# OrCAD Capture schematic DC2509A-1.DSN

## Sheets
1 PAGE2: size Custom; title: MULTI-SOURCE EH DEMOBOARD WITH BATTERY CHARGERS; rev: 1; note: DEMO CIRCUIT 2509A
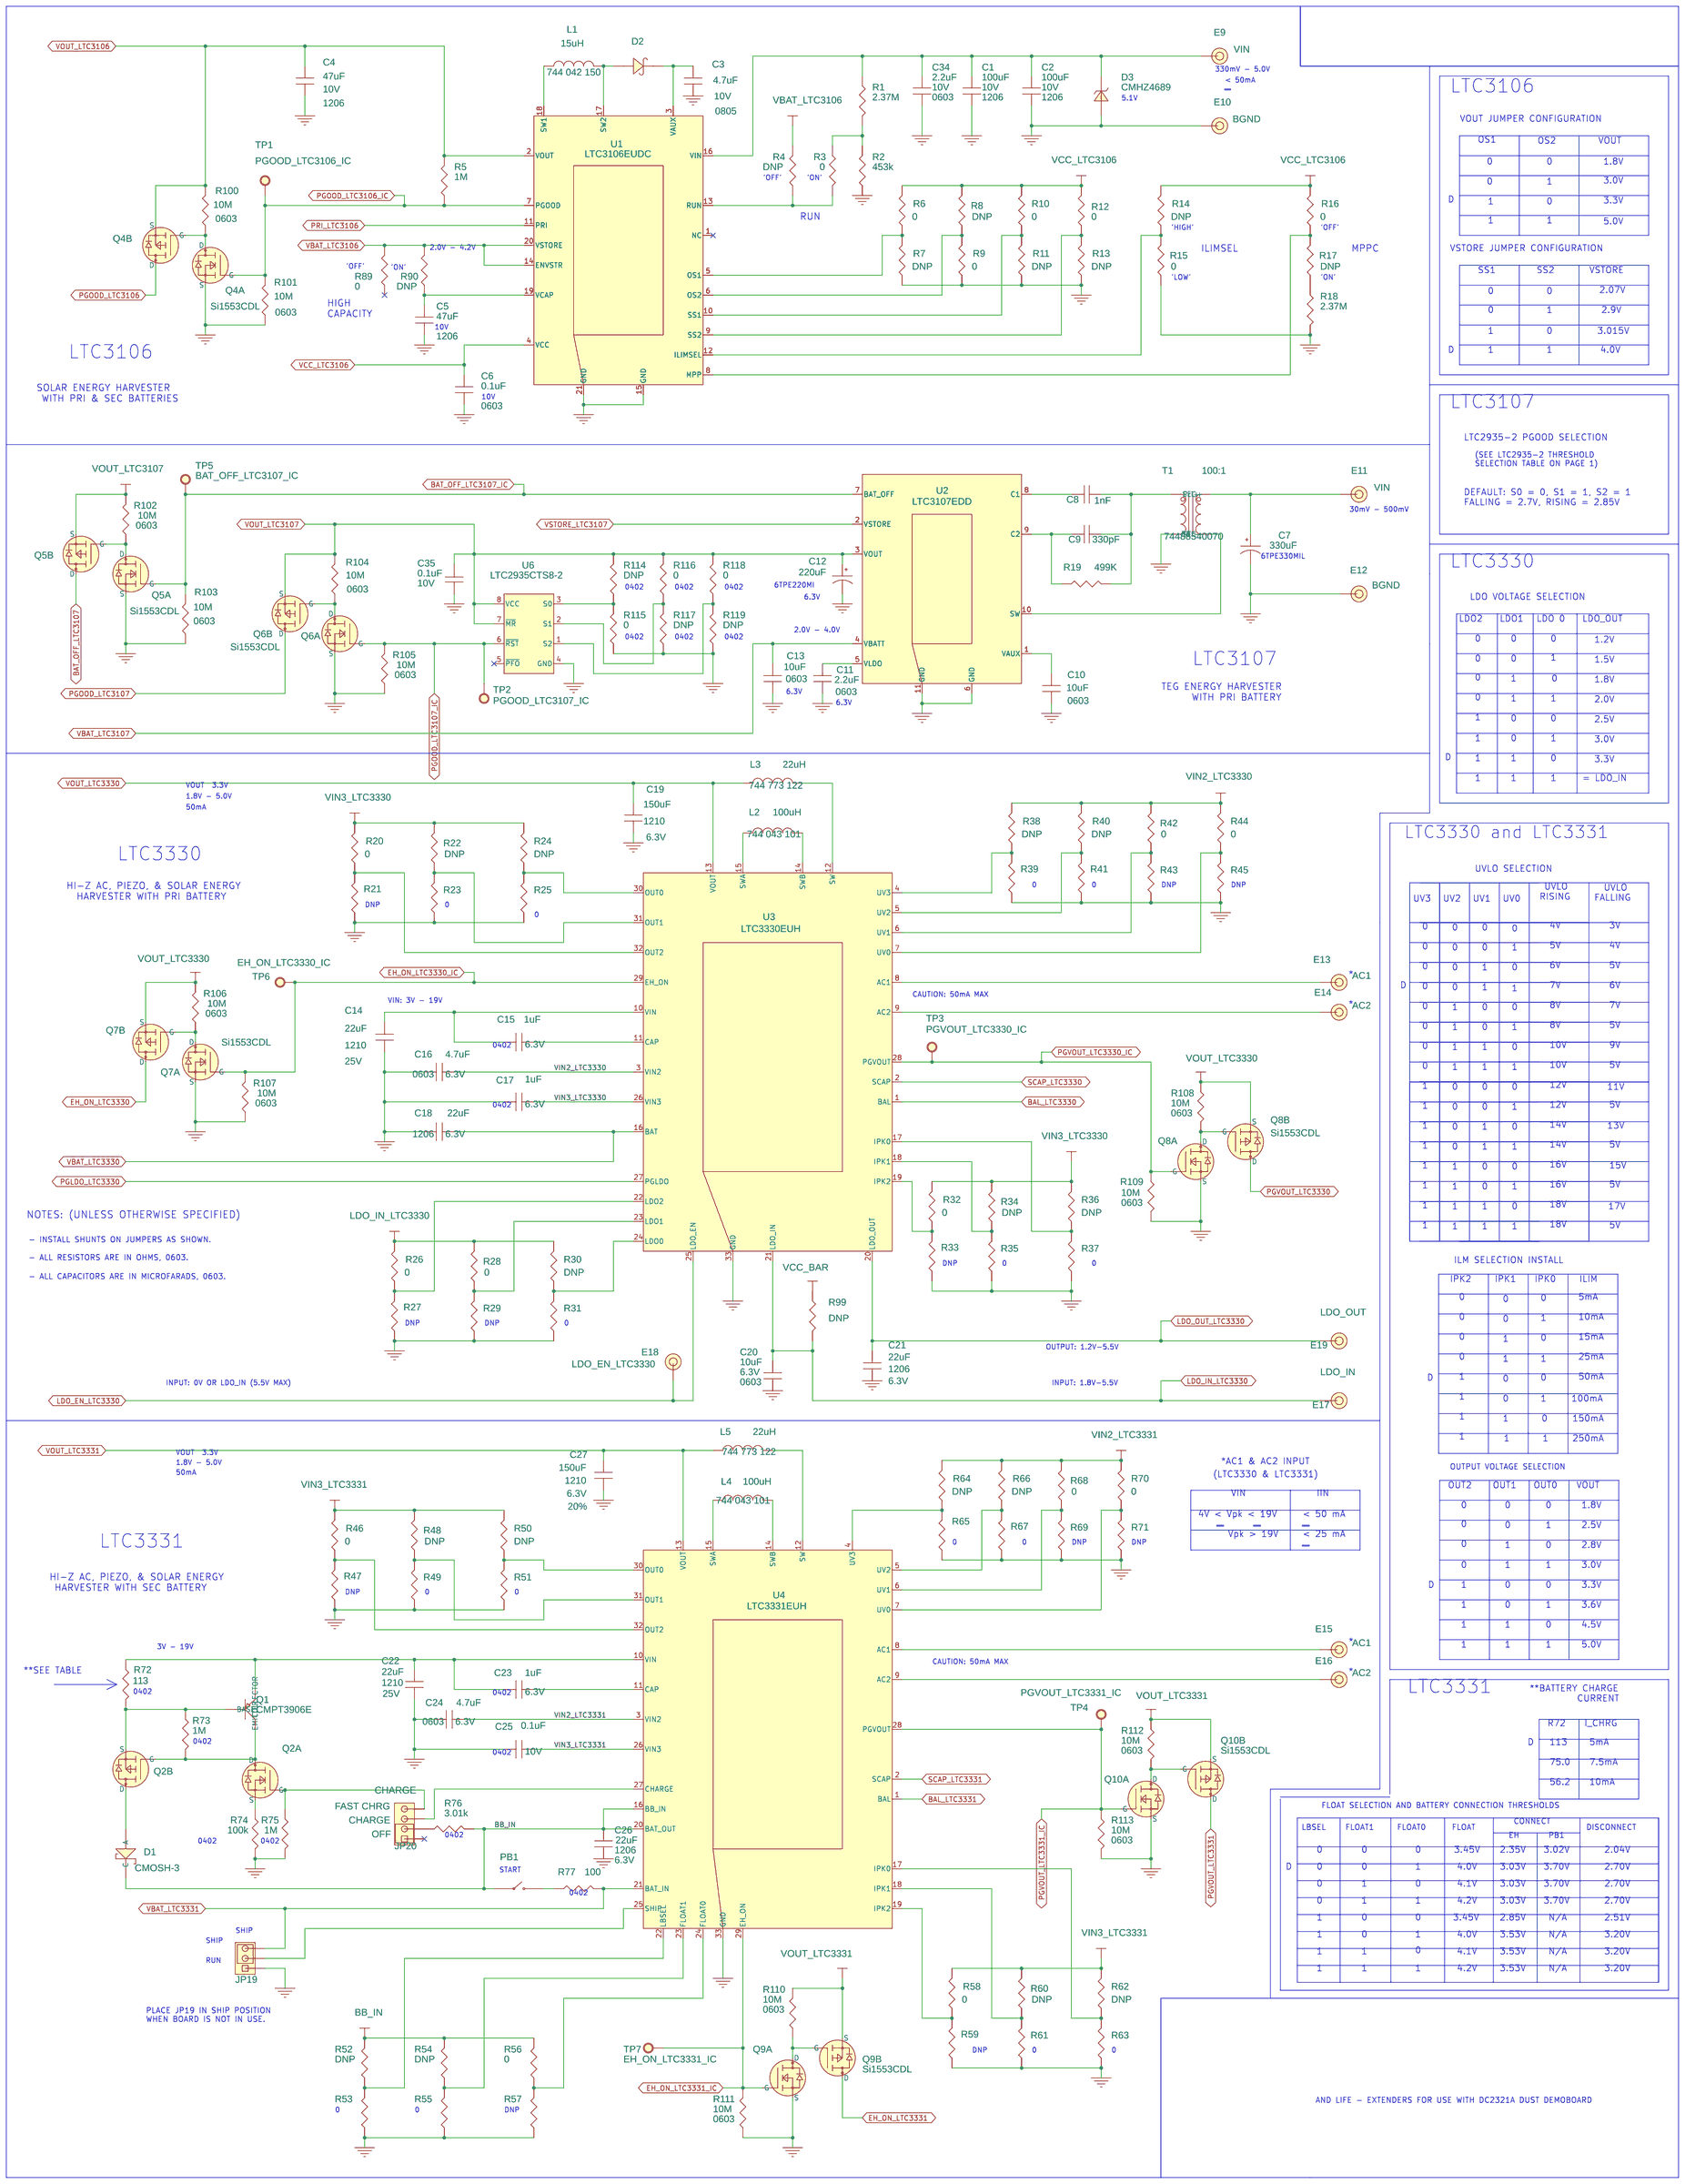
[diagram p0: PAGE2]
2 PAGE1: size Custom
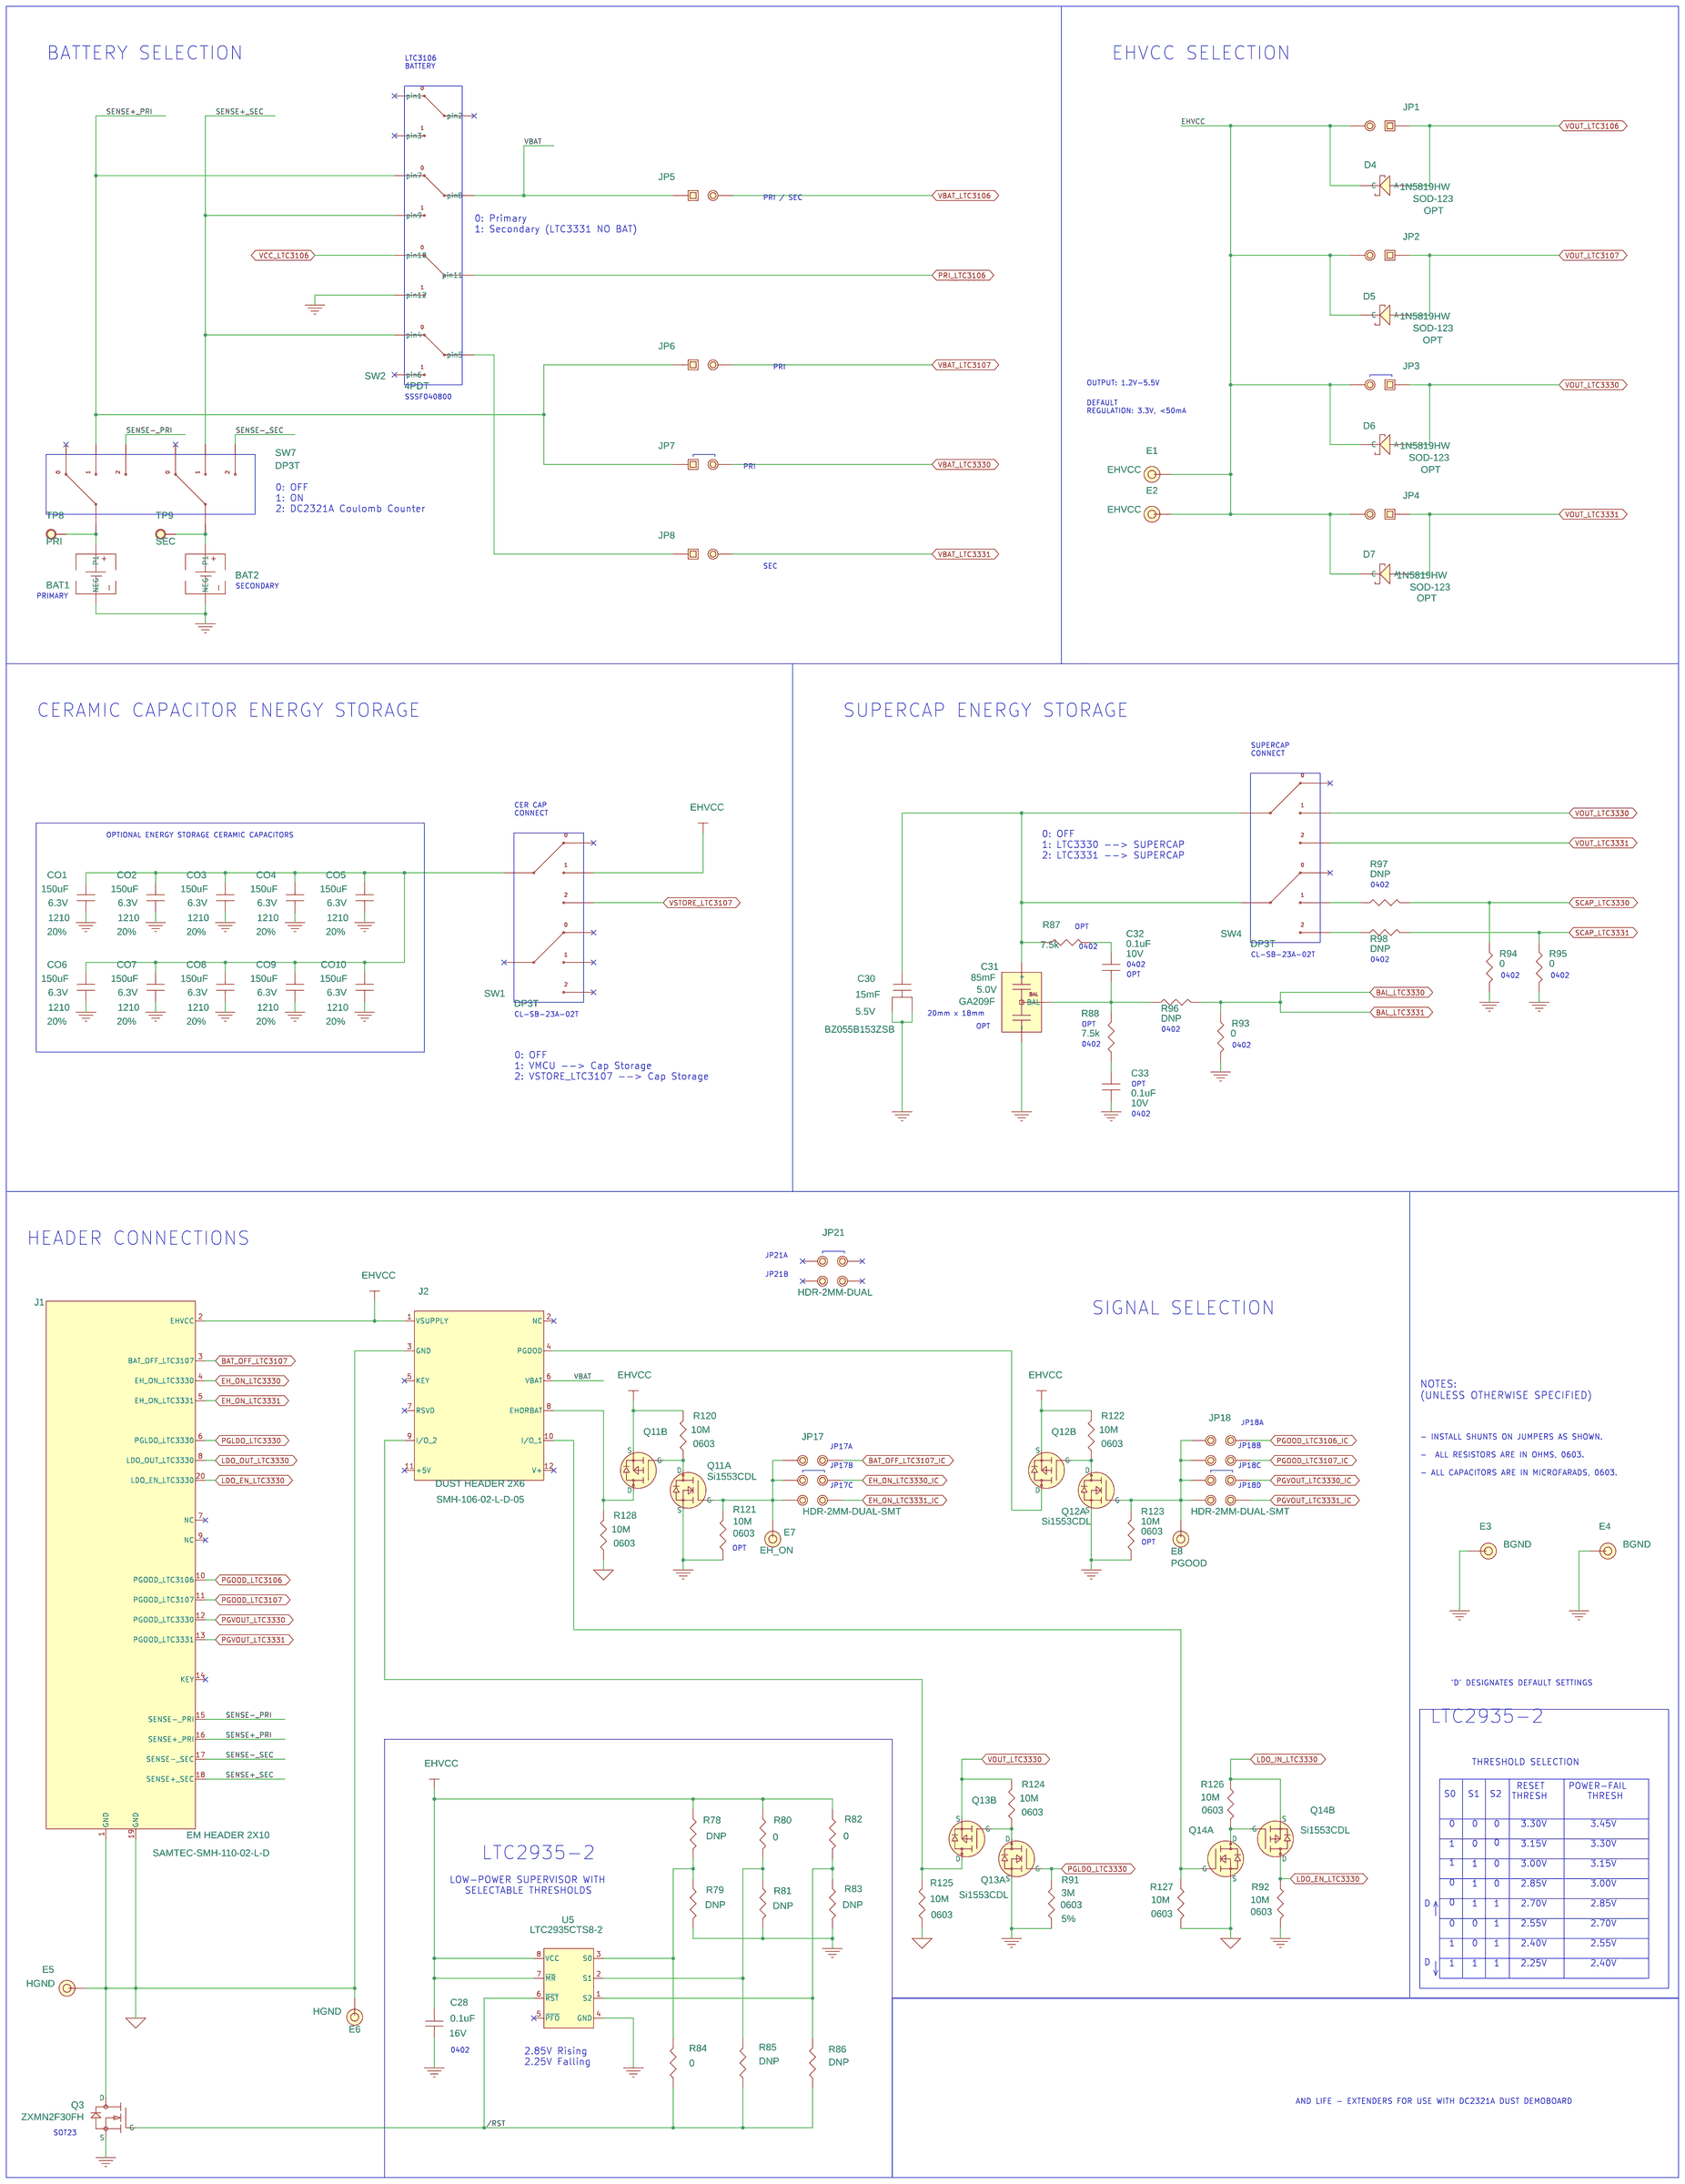
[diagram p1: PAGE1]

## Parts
sheet PAGE1
BAT1  CR2032  [BATTHOLD-WU-79527141]
BAT2  SMTU2032-LF  [BATTHOLD-WU-79527141]
C28  0.1uF  [0402-SMALL]
C30  15mF  [CAPAVX-BZ05]
C31  85mF  [CAP\CAP-XX\HA-202F]
C32  0.1uF  [0402]
C33  0.1uF  [0402]
CO1  150uF  [1210]
CO2  150uF  [1210]
CO3  150uF  [1210]
CO4  150uF  [1210]
CO5  150uF  [1210]
CO6  150uF  [1210]
CO7  150uF  [1210]
CO8  150uF  [1210]
CO9  150uF  [1210]
CO10  150uF  [1210]
D4  1N5819HW  [SOD-123]
D5  1N5819HW  [SOD-123]
D6  1N5819HW  [SOD-123]
D7  1N5819HW  [SOD-123]
E1  EHVCC  [MILL-MAX-2308]
E2  EHVCC  [MILL-MAX-2308]
E3  BGND  [MILL-MAX-2308]
E4  BGND  [MILL-MAX-2308]
E5  HGND  [MILL-MAX-2308]
E6  HGND  [MILL-MAX-2308]
E7  EH_ON  [MILL-MAX-2308]
E8  PGOOD  [MILL-MAX-2308]
J1  EM HEADER 2X10  [SAMTEC-SMH-110-02-L-D]
J2  DUST HEADER 2X6  [SMH-12PIN-100-DUST]
JP1  Sgl. Row 3 Pins 2mm Ctrs.  [TMM-102-01-T-S-SM]
JP2  Sgl. Row 3 Pins 2mm Ctrs.  [TMM-102-01-T-S-SM]
JP3  Sgl. Row 3 Pins 2mm Ctrs.  [TMM-102-01-T-S-SM]
JP4  Sgl. Row 3 Pins 2mm Ctrs.  [TMM-102-01-T-S-SM]
JP5  Sgl. Row 3 Pins 2mm Ctrs.  [TMM-102-01-T-S-SM]
JP6  Sgl. Row 3 Pins 2mm Ctrs.  [TMM-102-01-T-S-SM]
JP7  Sgl. Row 3 Pins 2mm Ctrs.  [TMM-102-01-T-S-SM]
JP8  Sgl. Row 3 Pins 2mm Ctrs.  [TMM-102-01-T-S-SM]
JP17  2pins 2mm Ctrs.  [HDR-WURTH-2MM-DUAL-SMT-62100621921]
JP18  2pins 2mm Ctrs.  [HDR-WURTH-2MM-DUAL-SMT-62100821921]
JP21  2pins 2mm Ctrs.  [WURTH_2MM_DUAL_PIN_HDR]
Q3  ZXMN2F30FH  [ZETEX-SOT23]
Q11  Si1553DL  [SC70-6]  (sections A,B)
Q12  Si1553DL  [SC70-6]  (sections A,B)
Q13  Si1553DL  [SC70-6]  (sections A,B)
Q14  Si1553DL  [SC70-6]  (sections A,B)
R78  DNP  [0402-SMALL]
R79  DNP  [0402-SMALL]
R80  0  [0402-SMALL]
R81  DNP  [0402-SMALL]
R82  0  [0402-SMALL]
R83  DNP  [0402-SMALL]
R84  0  [0402-SMALL]
R85  DNP  [0402-SMALL]
R86  DNP  [0402-SMALL]
R87  7.5k  [0402]
R88  7.5k  [0402]
R91  3M  [0603]
R92  10M  [0603]
R93  0  [0402-SMALL]
R94  0  [0402-SMALL]
R95  0  [0402-SMALL]
R96  DNP  [0402-SMALL]
R97  DNP  [0402-SMALL]
R98  DNP  [0402-SMALL]
R120  10M  [0603]
R121  10M  [0603]
R122  10M  [0603]
R123  10M  [0603]
R124  10M  [0603]
R125  10M  [0603]
R126  10M  [0603]
R127  10M  [0603]
R128  10M  [0603]
SW1  DP3T  [SLIDE_SW-DP3T-CL-SB-23A-02T]
SW2  4PDT  [SW-VERTICAL-4PDT-SSSF040800]
SW4  DP3T  [SLIDE_SW-DP3T-CL-SB-23A-02T]
SW7  DP3T  [SLIDE_SW-DP3T-CL-SB-23A-02T]
TP8  PRI  [TP]
TP9  SEC  [TP]
U5  LTC2935CTS8-2  [SOT23-8L]
sheet PAGE2
C1  100uF  [1206]
C2  100uF  [1206]
C3  4.7uF  [0805]
C4  47uF  [1206]
C5  47uF  [1206]
C6  0.1uF  [0603]
C7  330uF  [POSCAP-SANYO-TPC-D2]
C8  1nF  [0603]
C9  330pF  [0603]
C10  10uF  [0603]
C11  2.2uF  [0603]
C12  220uF  [POSCAP-SANYO-TPC-D2]
C13  10uF  [0603]
C14  22uF  [1210]
C15  1uF  [0402]
C16  4.7uF  [0603]
C17  1uF  [0402]
C18  22uF  [1206]
C19  150uF  [1210]
C20  10uF  [0603]
C21  22uF  [1206]
C22  22uF  [1210]
C23  1uF  [0402-SMALL]
C24  4.7uF  [0603]
C25  0.1uF  [0402-SMALL]
C26  22uF  [1206]
C27  150uF  [1210]
C34  2.2uF  [0603]
C35  0.1uF  [0402-SMALL]
D1  CMOSH-3  [DIODE-SHOTTKY-CMOSH-3]
D2  1A/20V  [SOD323-NXP]
D3  CMHZ4689  [SOD-123]
E9  VIN  [MILL-MAX-2308]
E10  BGND  [MILL-MAX-2308]
E11  VIN  [MILL-MAX-2308]
E12  BGND  [MILL-MAX-2308]
E13  AC1  [MILL-MAX-2308]
E14  AC2  [MILL-MAX-2308]
E15  AC1  [MILL-MAX-2308]
E16  AC2  [MILL-MAX-2308]
E17  LDO_IN  [MILL-MAX-2308]
E18  LDO_EN_LTC3330  [MILL-MAX-2308]
E19  LDO_OUT  [MILL-MAX-2308]
JP19  HD1X3-079  [HD1X3-079]
JP20  HD1X4-079  [HD1X4-079]
L1  15uH  [IND-WE-744042150]
L2  100uH  [IND-WE-744043101]
L3  22uH  [IND-WE732773220]
L4  100uH  [IND-WE-744043101]
L5  22uH  [IND-WE732773220]
PB1  WURTH- 434 111 025 826  [SW-WURTH-434-111-025-826]
Q1  CMPT3906E  [SOT-23]
Q2  NDS9952A  [SUPERSOT-6]  (sections A,B)
Q4  Si1553DL  [SC70-6]  (sections A,B)
Q5  Si1553DL  [SC70-6]  (sections A,B)
Q6  Si1553DL  [SC70-6]  (sections A,B)
Q7  Si1553DL  [SC70-6]  (sections A,B)
Q8  Si1553DL  [SC70-6]  (sections A,B)
Q9  Si1553DL  [SC70-6]  (sections A,B)
Q10  Si1553DL  [SC70-6]  (sections A,B)
R1  2.37M  [0603]
R2  453k  [0603]
R3  0  [0603]
R4  DNP  [0603]
R5  1M  [0603]
R6  0  [0603]
R7  DNP  [0603]
R8  DNP  [0603]
R9  0  [0603]
R10  0  [0603]
R11  DNP  [0603]
R12  0  [0603]
R13  DNP  [0603]
R14  DNP  [0603]
R15  0  [0603]
R16  0  [0603]
R17  DNP  [0603]
R18  2.37M  [0603]
R19  499K  [0603]
R20  0  [0603]
R21  0  [0603]
R22  DNP  [0603]
R23  0  [0603]
R24  DNP  [0603]
R25  0  [0603]
R26  0  [0603]
R27  0  [0603]
R28  0  [0603]
R29  0  [0603]
R30  DNP  [0603]
R31  0  [0603]
R32  0  [0603]
R33  0  [0603]
R34  DNP  [0603]
R35  0  [0603]
R36  DNP  [0603]
R37  0  [0603]
R38  DNP  [0603]
R39  0  [0603]
R40  DNP  [0603]
R41  0  [0603]
R42  0  [0603]
R43  0  [0603]
R44  0  [0603]
R45  0  [0603]
R46  0  [0603]
R47  0  [0603]
R48  DNP  [0603]
R49  0  [0603]
R50  DNP  [0603]
R51  0  [0603]
R52  DNP  [0603]
R53  0  [0603]
R54  DNP  [0603]
R55  0  [0603]
R56  0  [0603]
R57  0  [0603]
R58  0  [0603]
R59  0  [0603]
R60  DNP  [0603]
R61  0  [0603]
R62  DNP  [0603]
R63  0  [0603]
R64  DNP  [0603]
R65  0  [0603]
R66  DNP  [0603]
R67  0  [0603]
R68  0  [0603]
R69  0  [0603]
R70  0  [0603]
R71  0  [0603]
R72  113  [0402-SMALL]
R73  1M  [0402-SMALL]
R74  100k  [0402-SMALL]
R75  1M  [0402-SMALL]
R76  3.01k  [0402-SMALL]
R77  100  [0402-SMALL]
R89  0  [0603]
R90  DNP  [0603]
R99  DNP  [0603]
R100  10M  [0603]
R101  10M  [0603]
R102  10M  [0603]
R103  10M  [0603]
R104  10M  [0603]
R105  10M  [0603]
R106  10M  [0603]
R107  10M  [0603]
R108  10M  [0603]
R109  10M  [0603]
R110  10M  [0603]
R111  10M  [0603]
R112  10M  [0603]
R113  10M  [0603]
R114  DNP  [0402-SMALL]
R115  0  [0402-SMALL]
R116  0  [0402-SMALL]
R117  DNP  [0402-SMALL]
R118  0  [0402-SMALL]
R119  DNP  [0402-SMALL]
T1  74488540070  [TRANS-WE-74488540070]
TP1  PGOOD_LTC3106_IC  [TP]
TP2  PGOOD_LTC3107_IC  [TP]
TP3  PGVOUT_LTC3330_IC  [TP]
TP4  PGVOUT_LTC3331_IC  [TP]
TP5  BAT_OFF_LTC3107_IC  [TP]
TP6  EH_ON_LTC3330_IC  [TP]
TP7  EH_ON_LTC3331_IC  [TP]
U1  LTC3106EUDC  [QFN20EUDC-3X4]
U2  LTC3107EDD  [DFN(10)3MMX3MM]
U3  LTC3330EUH  [QFN(32)(UH)5MMX5MM]
U4  LTC3331EUH  [QFN(32)(UH)5MMX5MM]
U6  LTC2935CTS8-2  [SOT23-8L]

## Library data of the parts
BAT1 BAT2 = HU2032_2
C28 = C1608X5R0J475M: 1st Part Field: 16V; 2nd Part Field: 0402; 3rd Part Field: CHIP, X5R; 4th Part Field: MUR; 5th Part Field: GRM188R60J106ME47; 7th Part Field: CAP, X5R; Critical: T; Layer: T; MPN: GRM155R71C104KA88; Manufacturer: MUR; Populate: T; Size: 0402; Tempco: JIS-B; Tolerance: 10%; Voltage: 6.3Vmin
C30 = CAPACITOR_0: PART NUMBER: BZ055B153ZSB; Voltage: 5.5V
C31 = SUPERCAP_CAP-XX_HZ-SERIES_5: Part Number: GA209F; RATING: 5.0V; size: 20mm x 15mm
C25 C32 C33 = CAPACITOR: Voltage: 10V
C26 C27 CO1-CO10 = CAPACITOR: Tolerance: 20%; Voltage: 6.3V
D4-D7 = DIODE_SCHOTTKY: FIELD 99: OPT
E1-E19 = E_1: STATUS: 1.6V, 1.8V, 2.0V OR 2.5V @ 15A
J1 = HEADER2X7_9: OPN: SMH-110-02-L-D
J2 = HEADER2X7_0: OPN: SMH-106-02-L-D-05
JP1-JP8 = HD1X3_6: 10th Part Field: OFF; 12th Part Field: VSTORE; 9th Part Field: ON
JP17 = HDR-2MM-DUAL-SMT-62100821_0: 5th Part Field: 621 008 21; 9th Part Field: HDR-2MM-DUAL-SMT
JP18 = HDR-2MM-DUAL-SMT-62100821_2: 5th Part Field: 621 008 21; 9th Part Field: HDR-2MM-DUAL-SMT
JP21 = HDR-2MM-DUAL-SMT-62100821_3: 5th Part Field: 620 002 111 21; 9th Part Field: HDR-2MM-DUAL
Q3 = ZVN3306_0
Q4 Q5 Q8 Q9 Q11-Q14 = NDC7001C_5: COMPONENT: Si1553CDL
R3 R4 R6-R17 R20-R90 R92-R128 = RESISTOR
R91 = RESISTOR: TOLERANCE: 5%
SW1 SW4 = SW-DP3T_0
SW2 = SW-4PDT_3
SW7 = SW-DP3T_1
TP1-TP9 = Large_Turret_1
U5 U6 = MS8_5
C1 = Capacitor_1812_2: Voltage Rating: 10V
C2 = Capacitor_1812_1: Voltage Rating: 10V
C3 = Capacitor_0805: VOLTAGE RATING: 10V
C4 = Capacitor_1210_1: VOLTAGE RATING: 10V
C5 = Capacitor_1210
C6 = Capacitor_0805_1
C7 C12 = CAPACITOR_POL
C8 C9 = CAP_NP
C10 = Capacitor_0805_4
C11 = Capacitor_0805_2
C13 = Capacitor_0805_3
C14 C22 = CAPACITOR: Voltage: 25V
C15-C21 C23 C24 = CAPACITOR: Voltage: 6.3V
C34 = Capacitor_1812: Voltage Rating: 10V
C35 = C1608X5R0J475M: 1st Part Field: 10V; 2nd Part Field: 0402; 3rd Part Field: CHIP, X5R; 4th Part Field: MUR; 5th Part Field: GRM188R60J106ME47; 7th Part Field: CAP, X5R; Critical: T; Layer: T; MPN: GRM155R71C104KA88; Manufacturer: MUR; Populate: T; Size: 0402; Tempco: JIS-B; Tolerance: 10%; Voltage: 6.3Vmin
D1 = CMSH3-MA
D2 = PMEG2010EA_0: 6th Part Field: (OPT)
D3 = AD589_TO_1
JP19 = HD1X3_12
JP20 = HD1X4_2: TEXT: OFF; TEXT 4: CHARGE; TEXT2: CHARGE; TEXT3: FAST CHRG
L1 = INDUCTOR: PART NUMBER: 744 042 150
L2 L4 = INDUCTOR: PART NUMBER: 744 043 101
L3 L5 = INDUCTOR: PART NUMBER: 744 773 122
PB1 = SWITCH-TACT-SMD_0
Q1 = CMPT3906E
Q2 = NDC7001C_0
Q6 Q7 Q10 = NDC7001C_12: COMPONENT: Si1553CDL
R1 R2 R5 R18 R19 = R: V: 1%
T1 = LPR6235_0: TURNS RATIO: 100:1
U1 = LTC3106_21
U2 = LTC3107EDD_21
U3 = LTC3330EUH_48
U4 = LTC3330EUH_52

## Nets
GND: BAT1.2(NEG) BAT2.2(NEG) C1.2 C2.2 C3.2 C4.2 C5.2 C6.2 C7.2(-) C10.2 C11.2 C12.2(-) C13.2 C14.2 C16.1 C17.1 C18.1 C19.2 C20.2 C21.2 C22.2 C24.1 C25.1 C26.1 C27.2 C28.1 C30.2 C30.3 C31.1(-) C33.1 C34.2 C35.1 CO1.2 CO2.2 CO3.2 CO4.2 CO5.2 CO6.2 CO7.2 CO8.2 CO9.2 CO10.2 D3.2(A) E3.1(A) E4.1(A) E10.1(A) E12.1(A) JP19.1 Q3.2(S) Q4.1(S) Q5.1(S) Q6.1(S) Q7.1(S) Q8.1(S) Q9.1(S) Q10.1(S) Q11.1(S) Q12.1(S) Q13.1(S) R2.1 R7.1 R9.1 R11.1 R13.1 R15.1 R18.2 R21.1 R23.1 R25.1 R27.1 R29.1 R31.1 R33.1 R35.1 R37.1 R39.1 R41.1 R43.1 R45.1 R47.1 R49.1 R51.1 R53.1 R55.1 R57.1 R59.1 R61.1 R63.1 R65.1 R67.1 R69.1 R71.1 R74.2 R75.2 R79.2 R81.2 R83.2 R91.1 R92.2 R93.2 R94.2 R95.2 R101.2 R103.2 R105.2 R107.2 R109.2 R111.1 R113.2 R115.1 R117.1 R119.1 R121.2 R123.2 SW2.12(pin12) T1.3(SEC-) U1.15(GND) U1.21(GND) U2.6(GND) U2.11(GND) U3.33(GND) U4.33(GND) U5.4(GND) U6.4(GND)
GND_SIGNAL: E5.1(A) E6.1(A) J1.1(GND) J1.19(GND) J2.3(GND) Q3.3(D) Q14.1(S) R125.2 R127.2 R128.2
VBAT: J2.6(VBAT) JP5.1 SW2.8(pin8)
VBAT_LTC3106: JP5.2 R4.2 R89.2 R90.2 U1.14(ENVSTR) U1.20(VSTORE)
VBAT_LTC3107: C13.1 JP6.2 U2.4(VBATT)
VBAT_LTC3330: C18.2 JP7.2 U3.16(BAT)
VBAT_LTC3331: JP8.2 JP19.3 R77.2 U4.21(BAT_IN)
VCC_LTC3106: C6.1 R6.2 R8.2 R10.2 R12.2 R14.2 R16.2 SW2.10(pin10) U1.4(VCC)
VIN2_LTC3330: C16.2 R38.2 R40.2 R42.2 R44.2 U3.3(VIN2)
VIN2_LTC3331: C24.2 R64.2 R66.2 R68.2 R70.2 U4.3(VIN2)
VIN3_LTC3330: C17.2 R20.2 R22.2 R24.2 R32.2 R34.2 R36.2 U3.26(VIN3)
VIN3_LTC3331: C25.2 R46.2 R48.2 R50.2 R58.2 R60.2 R62.2 U4.26(VIN3)
/RST: Q3.1(G) R84.2 R85.2 R86.2 U5.6(~{RST})
BAL_LTC3330: R93.1 R96.2 U3.1(BAL) U4.1(BAL)
BAT_OFF_LTC3107: J1.3(BAT_OFF_LTC3107) Q5.3(D)
BAT_OFF_LTC3107_IC: JP17.1 Q5.2(G) R103.1 TP5.1 U2.7(BAT_OFF)
BB_IN: C26.2 D1.1(C) PB1.1(pin1) R52.2 R54.2 R56.2 R76.2 U4.16(BB_IN) U4.20(BAT_OUT)
EH_ON_LTC3330: J1.4(EH_ON_LTC3330) Q7.3(D)
EH_ON_LTC3330_IC: JP17.3 Q7.2(G) R107.1 TP6.1 U3.29(EH_ON)
EH_ON_LTC3331: J1.5(EH_ON_LTC3331) Q9.3(D)
EH_ON_LTC3331_IC: JP17.5 Q9.2(G) R111.2 TP7.1 U4.29(EH_ON)
EHVCC: C28.2 D4.1(C) D5.1(C) D6.1(C) D7.1(C) E1.1(A) E2.1(A) J1.2(EHVCC) J2.1(VSUPPLY) JP1.2 JP2.2 JP3.2 JP4.2 Q11.4(S) Q12.4(S) R78.1 R80.1 R82.1 R120.1 R122.1 SW1.2 U5.7(~{MR}) U5.8(VCC)
LDO_EN_LTC3330: E18.1(A) J1.20(LDO_EN_LTC3330) Q14.3(D) R92.1 U3.25(LDO_EN)
LDO_IN_LTC3330: C20.1 E17.1(A) Q14.4(S) R26.2 R28.2 R30.2 R99.2 R126.1 U3.21(LDO_IN)
LDO_OUT_LTC3330: C21.1 E19.1(A) J1.8(LDO_OUT_LTC3330) U3.20(LDO_OUT)
PGLDO_LTC3330: J1.6(PGLDO_LTC3330) Q13.2(G) R91.2 U3.27(PGLDO)
PGOOD_LTC3106: J1.10(PGOOD_LTC3106) Q4.3(D)
PGOOD_LTC3106_IC: JP18.1 Q4.2(G) R5.1 R101.1 TP1.1 U1.7(PGOOD)
PGOOD_LTC3107: J1.11(PGOOD_LTC3107) Q6.3(D)
PGOOD_LTC3107_IC: JP18.3 Q6.2(G) R105.1 TP2.1 U6.6(~{RST})
PGVOUT_LTC3330: J1.12(PGOOD_LTC3330) Q8.3(D)
PGVOUT_LTC3330_IC: JP18.5 Q8.2(G) R109.1 TP3.1 U3.28(PGVOUT)
PGVOUT_LTC3331: J1.13(PGOOD_LTC3331) Q10.3(D)
PGVOUT_LTC3331_IC: JP18.7 Q10.2(G) R113.1 TP4.1 U4.28(PGVOUT)
PRI_LTC3106: SW2.11(pin11) U1.11(PRI)
SCAP_LTC3330: R94.1 R97.2 U3.2(SCAP)
SCAP_LTC3331: R95.1 R98.2 U4.2(SCAP)
SENSE+_PRI: J1.16(SENSE+_PRI) JP6.1 JP7.1 SW2.7(pin7) SW7.2
SENSE+_SEC: J1.18(SENSE+_SEC) SW2.4(pin4) SW2.9(pin9) SW7.6
SENSE-_PRI: J1.15(SENSE-_PRI) SW7.4
SENSE-_SEC: J1.17(SENSE-_SEC) SW7.8
VOUT_LTC3106: C4.1 D4.2(A) JP1.1 Q4.4(S) R5.2 R100.1 U1.2(VOUT)
VOUT_LTC3107: C12.1(+) C35.2 D5.2(A) JP2.1 Q5.4(S) Q6.4(S) R102.1 R104.1 R114.2 R116.2 R118.2 U2.3(VOUT) U6.7(~{MR}) U6.8(VCC)
VOUT_LTC3330: C19.1 D6.2(A) JP3.1 L3.2 Q7.4(S) Q8.4(S) Q13.4(S) R99.1 R106.1 R108.1 R124.1 SW4.2 U3.13(VOUT)
VOUT_LTC3331: C27.1 D7.2(A) JP4.1 L5.2 Q9.4(S) Q10.4(S) R110.2 R112.1 SW4.4 U4.13(VOUT)
VSTORE_LTC3107: SW1.4 U2.2(VSTORE)
N03463: CO1.1 CO2.1 CO3.1 CO4.1 CO5.1 CO6.1 CO7.1 CO8.1 CO9.1 CO10.1 SW1.3
N04521: C30.1 C31.2(+) R87.1 SW4.3 SW4.7
N04553: C33.2 R88.1
N04669: C32.2 R87.2
N04677: C31.3(BAL) C32.1 R88.2 R96.1
N13549: R14.1 R15.2 U1.12(ILIMSEL)
N13649: D2.2(A) L1.2 U1.17(SW2)
N13903: L1.1 U1.18(SW1)
N14133: R10.1 R11.2 U1.10(SS1)
N14341: R6.1 R7.2 U1.5(OS1)
N14353: R8.1 R9.2 U1.6(OS2)
N14361: R12.1 R13.2 U1.9(SS2)
N79433: C3.1 D2.1(K) U1.3(VAUX)
N90671: C1.1 C2.1 C34.1 D3.1(C) E9.1(A) R1.1 U1.16(VIN)
N195018: C10.1 U2.1(VAUX)
N253541: C8.2 U2.8(C1)
N254060: C8.1 C9.1 R19.1 T1.4(SEC+)
N256149: C9.2 R19.2 U2.9(C2)
N259328: T1.2(PRI-) U2.10(SW)
N262764: C7.1(+) E11.1(A) T1.1(Pri+)
N297149: R20.1 R21.2 U3.32(OUT2)
N297161: R22.1 R23.2 U3.31(OUT1)
N305370: R40.1 R41.2 U3.5(UV2)
N305418: R42.1 R43.2 U3.6(UV1)
N305494: R44.1 R45.2 U3.7(UV0)
N325168: R34.1 R35.2 U3.18(IPK1)
N325176: R36.1 R37.2 U3.17(IPK0)
N342106: R24.1 R25.2 U3.30(OUT0)
N364385: L2.2 U3.14(SWB)
N367404: L2.1 U3.15(SWA)
N368250: L3.1 U3.12(SW)
N387580: R38.1 R39.2 U3.4(UV3)
N401789: E13.1(A) U3.8(AC1)
N402194: E14.1(A) U3.9(AC2)
N570733: R16.1 R17.2 U1.8(MPP)
N647158: R32.1 R33.2 U3.19(IPK2)
N667015: Q1.1(BASE) Q2.2(S) R72.2 R73.1
N667031: C22.1 C23.1 Q1.2(EMITTER) R72.1 U4.10(VIN)
N667183: Q1.3(COLLECTOR) Q2.3(G) Q2.6(D) R73.2
N667285: C23.2 U4.11(CAP)
N667609: D1.2(A) Q2.4(D)
N672234: R46.1 R47.2 U4.32(OUT2)
N672246: R48.1 R49.2 U4.31(OUT1)
N672254: R50.1 R51.2 U4.30(OUT0)
N674449: R68.1 R69.2 U4.6(UV1)
N674457: R70.1 R71.2 U4.7(UV0)
N674605: R66.1 R67.2 U4.5(UV2)
N674649: R64.1 R65.2 U4.4(UV3)
N697209: L4.2 U4.14(SWB)
N697818: L4.1 U4.15(SWA)
N698429: L5.1 U4.12(SW)
N715353: E15.1(A) U4.8(AC1)
N804598: JP20.4 Q2.1(G) R75.1
N850435: JP20.3 U4.27(CHARGE)
N877885: Q2.5(S) R74.1
N900104: R52.1 R53.2 U4.22(LBSEL)
N900116: R54.1 R55.2 U4.23(FLOAT1)
N958336: JP19.2 U4.25(SHIP)
N969746: R56.1 R57.2 U4.24(FLOAT0)
N1011619: E16.1(A) U4.9(AC2)
N1405916: JP8.1 SW2.5(pin5)
N1653283: PB1.2(pin2) R77.1
N1769866: R80.2 R81.1 R85.1 U5.2(S1)
N1782720: R78.2 R79.1 R84.1 U5.3(S0)
N1810210: R82.2 R83.1 R86.1 U5.1(S2)
N1865756: J2.4(PGOOD) Q12.3(D)
N1889377: J2.9(I/O_2) Q13.3(D) R125.1
N1895513: J2.10(I/O_1) Q14.2(G) R127.1
N2393749: J2.8(EHORBAT) Q11.3(D) R128.1
N3218720: BAT1.1(P1) SW7.3 TP8.1
N3229805: BAT2.1(P1) SW7.7 TP9.1
N3281968: C5.1 R90.1 U1.19(VCAP)
N3803315: R62.1 R63.2 U4.17(IPK0)
N3803331: R58.1 R59.2 U4.19(IPK2)
N3803335: R60.1 R61.2 U4.18(IPK1)
N6304381: Q10.5(G) Q10.6(D) R112.2
N6307549: Q9.5(G) Q9.6(D) R110.1
N6313161: Q8.5(G) Q8.6(D) R108.2
N6315704: Q5.5(G) Q5.6(D) R102.2
N6316606: Q4.5(G) Q4.6(D) R100.2
N6333249: R114.1 R115.2 U6.3(S0)
N6334947: R118.1 R119.2 U6.1(S2)
N6334965: R116.1 R117.2 U6.2(S1)
N6340037: Q6.5(G) Q6.6(D) R104.2
N6351705: R97.1 SW4.6
N6351709: R98.1 SW4.8
N6368449: E7.1(A) JP17.2 JP17.4 JP17.6 Q11.2(G) R121.1
N6469258: Q7.5(G) Q7.6(D) R106.2
N6471133: C14.1 C15.1 U3.10(VIN)
N6471137: C15.2 U3.11(CAP)
N6473790: R26.1 R27.2 U3.22(LDO2)
N6473794: R28.1 R29.2 U3.23(LDO1)
N6473798: R30.1 R31.2 U3.24(LDO0)
N6545649: C11.1 U2.5(VLDO)
N6574879: R1.2 R2.2 R3.1
N6574905: R3.2 R4.1 U1.13(RUN)
N6706860: E8.1(A) JP18.2 JP18.4 JP18.6 JP18.8 Q12.2(G) R123.1
N6715062: Q11.5(G) Q11.6(D) R120.2
N6717413: Q12.5(G) Q12.6(D) R122.2
N6719846: Q13.5(G) Q13.6(D) R124.2
N6720609: Q14.5(G) Q14.6(D) R126.2
N6854082: R17.1 R18.1
N6854083: JP20.2 R76.1

Not connected (* = marked no-connect by the designer): J1 7(NC)* 9(NC)* 14(KEY)*; J2 2(NC)* 5(KEY)* 7(RSVD)* 11(+5V)* 12(V+)*; JP20 1*; JP21 1* 2* 3* 4*; R89 1*; SW1 1* 5* 6* 7* 8*; SW2 1(pin1)* 2(pin2)* 3(pin3)* 6(pin6)*; SW4 1* 5*; SW7 1* 5*; U1 1(NC)*; U5 5(~{PFO})*; U6 5(~{PFO})*

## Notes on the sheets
sheet 1
- 330mV - 5.0V
- < 50mA
- LTC3106
- 5.1V
- VOUT JUMPER CONFIGURATION
- OS1
- OS2
- VOUT
- 0
- 0
- 1.8V
- 'OFF'
- 'ON'
- 0
- 1
- 3.0V
- D
- 1
- 0
- 3.3V
- RUN
- 1
- 1
- 5.0V
- 'HIGH'
- 'OFF'
- 2.0V - 4.2V
- ILIMSEL
- MPPC
- VSTORE JUMPER CONFIGURATION
- 'OFF'
- 'ON'
- SS1
- SS2
- VSTORE
- 'LOW'
- 'ON'
- 0
- 0
- 2.07V
- HIGH
  CAPACITY
- 0
- 1
- 2.9V
- 10V
- 1
- 0
- 3.015V
- LTC3106
- D
- 1
- 1
- 4.0V
- SOLAR ENERGY HARVESTER
   WITH PRI & SEC BATTERIES
- 10V
- LTC3107
- LTC2935-2 PGOOD SELECTION
- (SEE LTC2935-2 THRESHOLD
  SELECTION TABLE ON PAGE 1)
- DEFAULT: S0 = 0, S1 = 1, S2 = 1
  FALLING = 2.7V, RISING = 2.85V
- 30mV - 500mV
- 6TPE330MIL
- LTC3330
- 0402
- 0402
- 0402
- 6TPE220MI
- 6.3V
- LDO VOLTAGE SELECTION
- LDO2
- LDO1
- LDO 0
- LDO_OUT
- 2.0V - 4.0V
- 0402
- 0402
- 0402
- 0
- 0
- 0
- 1.2V
- LTC3107
- 0
- 0
- 1
- 1.5V
- 0
- 1
- 0
- 1.8V
- 6.3V
- TEG ENERGY HARVESTER
        WITH PRI BATTERY
- 6.3V
- 0
- 1
- 1
- 2.0V
- 1
- 0
- 0
- 2.5V
- 1
- 0
- 1
- 3.0V
- D
- 1
- 1
- 0
- 3.3V
- 1
- 1
- 1
- = LDO_IN
- VOUT  3.3V
- 1.8V - 5.0V
- 50mA
- LTC3330 and LTC3331
- LTC3330
- UVLO SELECTION
- HI-Z AC, PIEZO, & SOLAR ENERGY
    HARVESTER WITH PRI BATTERY
- 0
- 0
- DNP
- DNP
- UVLO
  RISING
- UVLO
  FALLING
- DNP
- 0
- UV3
- UV2
- UV1
- UV0
- 0
- 0
- 0
- 0
- 0
- 4V
- 3V
- 0
- 0
- 0
- 1
- 5V
- 4V
- 0
- 6V
- 5V
- *
- 0
- 1
- 0
- D
- 0
- 0
- 1
- 1
- 7V
- 6V
- VIN: 3V - 19V
- CAUTION: 50mA MAX
- *
- 0
- 1
- 0
- 0
- 8V
- 7V
- 8V
- 5V
- 0
- 1
- 0
- 1
- 0402
- 0
- 1
- 1
- 0
- 10V
- 9V
- 0
- 1
- 1
- 1
- 10V
- 5V
- 1
- 0
- 0
- 0
- 12V
- 11V
- 0402
- 1
- 0
- 0
- 1
- 12V
- 5V
- 1
- 0
- 1
- 0
- 14V
- 13V
- 1
- 0
- 1
- 1
- 14V
- 5V
- 1
- 1
- 0
- 0
- 16V
- 15V
- 1
- 1
- 0
- 1
- 16V
- 5V
- 1
- 1
- 1
- 0
- 18V
- 17V
- NOTES: (UNLESS OTHERWISE SPECIFIED)
- 1
- 18V
- 5V
- 1
- 1
- 1
- - INSTALL SHUNTS ON JUMPERS AS SHOWN.
- - ALL RESISTORS ARE IN OHMS, 0603.
- ILM SELECTION INSTALL
- DNP
- 0
- 0
- - ALL CAPACITORS ARE IN MICROFARADS, 0603.
- IPK2
- IPK1
- IPK0
- ILIM
- 0
- 0
- 0
- 5mA
- 0
- 0
- 1
- 10mA
- DNP
- DNP
- 0
- 0
- 1
- 0
- 15mA
- OUTPUT: 1.2V-5.5V
- 0
- 1
- 1
- 25mA
- D
- 1
- 0
- 0
- 50mA
- INPUT: 0V OR LDO_IN (5.5V MAX)
- INPUT: 1.8V-5.5V
- 1
- 0
- 1
- 100mA
- 1
- 1
- 0
- 150mA
- 1
- 1
- 1
- 250mA
- VOUT  3.3V
- 1.8V - 5.0V
- *AC1 & AC2 INPUT
- OUTPUT VOLTAGE SELECTION
- 50mA
- (LTC3330 & LTC3331)
- VIN
- IIN
- OUT2
- OUT1
- OUT0
- VOUT
- 0
- 0
- 0
- 1.8V
- 4V < Vpk < 19V
- < 50 mA
- 0
- 0
- 1
- 2.5V
- LTC3331
- 0
- 0
- DNP
- DNP
- Vpk > 19V
- < 25 mA
- 0
- 1
- 0
- 2.8V
- 0
- 1
- 1
- 3.0V
- HI-Z AC, PIEZO, & SOLAR ENERGY
   HARVESTER WITH SEC BATTERY
- D
- 1
- 0
- 0
- 3.3V
- DNP
- 0
- 0
- 1
- 0
- 1
- 3.6V
- 1
- 1
- 0
- 4.5V
- 3V - 19V
- *
- 1
- 1
- 1
- 5.0V
- **SEE TABLE
- CAUTION: 50mA MAX
- *
- LTC3331
- 0402
- 0402
- **BATTERY CHARGE
            CURRENT
- R72
- I_CHRG
- 0402
- D
- 113
- 5mA
- 0402
- 75.0
- 7.5mA
- 56.2
- 10mA
- FLOAT SELECTION AND BATTERY CONNECTION THRESHOLDS
- CONNECT
- 0402
- LBSEL
- FLOAT1
- FLOAT0
- FLOAT
- EH
- PB1
- DISCONNECT
- 0402
- 0402
- 0
- 0
- 0
- 3.45V
- 2.35V
- 3.02V
- 2.04V
- START
- D
- 0
- 0
- 1
- 4.0V
- 3.03V
- 3.70V
- 2.70V
- 0
- 1
- 0
- 4.1V
- 3.03V
- 3.70V
- 2.70V
- 0402
- 0
- 1
- 1
- 4.2V
- 3.03V
- 3.70V
- 2.70V
- 1
- 0
- 0
- 3.45V
- 2.85V
- N/A
- 2.51V
- SHIP
- SHIP
- 1
- 0
- 1
- 4.0V
- 3.53V
- N/A
- 3.20V
- 1
- 1
- 0
- 4.1V
- 3.53V
- N/A
- 3.20V
- RUN
- 1
- 1
- 1
- 4.2V
- 3.53V
- N/A
- 3.20V
- PLACE JP19 IN SHIP POSITION
  WHEN BOARD IS NOT IN USE.
- DNP
- 0
- 0
- AND LIFE - EXTENDERS FOR USE WITH DC2321A DUST DEMOBOARD
- 0
- 0
- DNP
sheet 2
- BATTERY SELECTION
- EHVCC SELECTION
- LTC3106
  BATTERY
- PRI / SEC
- 0: Primary
  1: Secondary (LTC3331 NO BAT)
- PRI
- OUTPUT: 1.2V-5.5V
- SSSF040800
- DEFAULT
  REGULATION: 3.3V, <50mA
- PRI
- 0: OFF
  1: ON
  2: DC2321A Coulomb Counter
- SEC
- SECONDARY
- PRIMARY
- CERAMIC CAPACITOR ENERGY STORAGE
- SUPERCAP ENERGY STORAGE
- SUPERCAP
  CONNECT
- CER CAP
  CONNECT
- OPTIONAL ENERGY STORAGE CERAMIC CAPACITORS
- 0: OFF
  1: LTC3330 --> SUPERCAP
  2: LTC3331 --> SUPERCAP
- 0402
- OPT
- 0402
- 0402
- CL-SB-23A-02T
- 0402
- OPT
- 0402
- 0402
- CL-SB-23A-02T
- 20mm x 18mm
- OPT
- OPT
- 0402
- 0402
- 0402
- 0: OFF
  1: VMCU --> Cap Storage
  2: VSTORE_LTC3107 --> Cap Storage
- OPT
- 0402
- HEADER CONNECTIONS
- JP21A
- JP21B
- SIGNAL SELECTION
- NOTES:
  (UNLESS OTHERWISE SPECIFIED)
- JP18A
- - INSTALL SHUNTS ON JUMPERS AS SHOWN.
- JP17A
- JP18B
- -  ALL RESISTORS ARE IN OHMS, 0603.
- JP17B
- JP18C
- - ALL CAPACITORS ARE IN MICROFARADS, 0603.
- JP17C
- JP18D
- OPT
- OPT
- 'D' DESIGNATES DEFAULT SETTINGS
- LTC2935-2
- THRESHOLD SELECTION
- RESET
  THRESH
- POWER-FAIL
      THRESH
- S0
- S1
- S2
- 0
- 0
- 0
- 3.30V
- 3.45V
- LTC2935-2
- 1
- 0
- 0
- 3.15V
- 3.30V
- 1
- 1
- 0
- 3.00V
- 3.15V
- LOW-POWER SUPERVISOR WITH
     SELECTABLE THRESHOLDS
- 0
- 1
- 0
- 2.85V
- 3.00V
- D
- 0
- 1
- 1
- 2.70V
- 2.85V
- 0
- 0
- 1
- 2.55V
- 2.70V
- 1
- 0
- 1
- 2.40V
- 2.55V
- D
- 1
- 1
- 1
- 2.25V
- 2.40V
- 0402
- 2.85V Rising
  2.25V Falling
- AND LIFE - EXTENDERS FOR USE WITH DC2321A DUST DEMOBOARD
- SOT23
